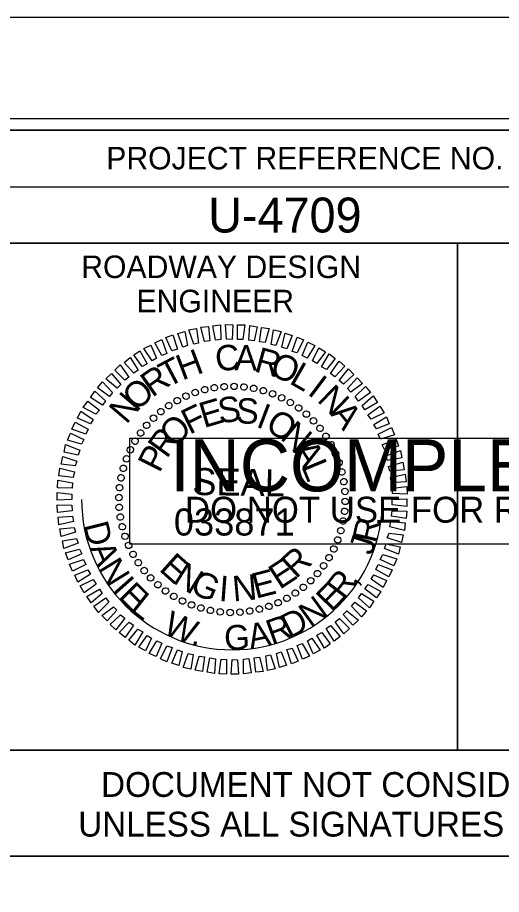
# Model space of a CAD drawing. Extents: x 1779926 to 1781626, y 618464 to 619564.
# Drawn here: x 1781395.5 to 1781502.7, y 619369.7 to 619564.2 of the extents above; entities that cross this region are included whole.
import ezdxf

# ---------------------------------------------------------------- set-up
doc = ezdxf.new("R2010")
doc.units = 0
for name, color, linetype in [('Old_Level_58', 7, 'Continuous'), ('Scratch_Level_0', 7, 'Continuous'), ('Sheet Data Field CELL', 7, 'Continuous'), ('Sheet Plot Border Inside CELL', 7, 'Continuous'), ('Sheet Plot Border Outside CELL', 7, 'Continuous'), ('Sheet Professional Seal CELL', 7, 'Continuous'), ('Sheet Profile CELL', 7, 'Continuous'), ('Sheet Profile Grid Major CELL', 7, 'Continuous'), ('Sheet Profile Grid Minor CELL', 7, 'Continuous'), ('Sheet Sticker Exception Certification CELL', 7, 'Continuous'), ('Sheet Sticker Incomplete CELL', 7, 'Continuous')]:
    doc.layers.add(name, color=color, linetype=linetype)

msp = doc.modelspace()

# ---------------------------------------------------------------- linework, layer by layer
at = {"layer": 'Old_Level_58'}
msp.add_lwpolyline([(1781392.9, 619378.14), (1781592.95, 619378.14), (1781592.95, 619314.19), (1781392.9, 619314.19)], close=True, dxfattribs=at)
at = {"layer": 'Scratch_Level_0'}
msp.add_arc((1781443.01, 619457.29), 33.36, 180, 360, dxfattribs=at)
at = {"layer": 'Sheet Plot Border Inside CELL'}
msp.add_lwpolyline([(1779938.96, 618486.64), (1781605.46, 618486.64), (1781605.46, 619541.74), (1779938.96, 619541.74)], close=True, dxfattribs=at)
at = {"layer": 'Sheet Plot Border Outside CELL'}
msp.add_lwpolyline([(1779925.96, 618464.19), (1781625.96, 618464.19), (1781625.96, 619564.19), (1779925.96, 619564.19)], close=True, dxfattribs=at)
at = {"layer": 'Sheet Professional Seal CELL'}
for p, q in [((1781434.81, 619481.04), (1781434.81, 619481.04)), ((1781436.91, 619481.64), (1781436.91, 619481.64)), ((1781439.11, 619482.04), (1781439.11, 619482.04)), ((1781441.26, 619482.34), (1781441.26, 619482.34)), ((1781443.46, 619482.39), (1781443.46, 619482.39)), ((1781445.66, 619482.24), (1781445.66, 619482.24)), ((1781447.81, 619481.89), (1781447.81, 619481.89)), ((1781449.91, 619481.44), (1781449.91, 619481.44)), ((1781430.86, 619479.24), (1781430.86, 619479.24)), ((1781432.81, 619480.24), (1781432.81, 619480.24)), ((1781452.01, 619480.74), (1781452.01, 619480.74)), ((1781454.01, 619479.84), (1781454.01, 619479.84)), ((1781428.96, 619478.09), (1781428.96, 619478.09)), ((1781455.96, 619478.84), (1781455.96, 619478.84)), ((1781457.76, 619477.59), (1781457.76, 619477.59)), ((1781425.56, 619475.34), (1781425.56, 619475.34)), ((1781427.21, 619476.84), (1781427.21, 619476.84)), ((1781459.51, 619476.24), (1781459.51, 619476.24)), ((1781424.06, 619473.79), (1781424.06, 619473.79)), ((1781461.06, 619474.74), (1781461.06, 619474.74)), ((1781422.71, 619472.04), (1781422.71, 619472.04)), ((1781462.56, 619473.09), (1781462.56, 619473.09)), ((1781463.81, 619471.34), (1781463.81, 619471.34)), ((1781421.46, 619470.24), (1781421.46, 619470.24)), ((1781464.96, 619469.44), (1781464.96, 619469.44)), ((1781420.46, 619468.29), (1781420.46, 619468.29)), ((1781465.96, 619467.49), (1781465.96, 619467.49)), ((1781419.56, 619466.29), (1781419.56, 619466.29)), ((1781466.76, 619465.49), (1781466.76, 619465.49)), ((1781418.86, 619464.19), (1781418.86, 619464.19)), ((1781418.41, 619462.09), (1781418.41, 619462.09)), ((1781467.36, 619463.39), (1781467.36, 619463.39)), ((1781418.06, 619459.94), (1781418.06, 619459.94)), ((1781467.76, 619461.19), (1781467.76, 619461.19)), ((1781417.91, 619457.74), (1781417.91, 619457.74)), ((1781468.06, 619459.04), (1781468.06, 619459.04)), ((1781443.01, 619457.29), (1781443.01, 619457.29)), ((1781468.11, 619456.84), (1781468.11, 619456.84)), ((1781417.96, 619455.54), (1781417.96, 619455.54)), ((1781467.96, 619454.64), (1781467.96, 619454.64)), ((1781418.26, 619453.39), (1781418.26, 619453.39)), ((1781467.61, 619452.49), (1781467.61, 619452.49)), ((1781418.66, 619451.19), (1781418.66, 619451.19)), ((1781467.16, 619450.39), (1781467.16, 619450.39)), ((1781419.26, 619449.09), (1781419.26, 619449.09)), ((1781466.46, 619448.29), (1781466.46, 619448.29)), ((1781420.06, 619447.09), (1781420.06, 619447.09)), ((1781465.56, 619446.29), (1781465.56, 619446.29)), ((1781421.06, 619445.14), (1781421.06, 619445.14)), ((1781464.56, 619444.34), (1781464.56, 619444.34)), ((1781422.21, 619443.24), (1781422.21, 619443.24)), ((1781463.31, 619442.54), (1781463.31, 619442.54)), ((1781423.46, 619441.49), (1781423.46, 619441.49)), ((1781461.96, 619440.79), (1781461.96, 619440.79)), ((1781424.96, 619439.84), (1781424.96, 619439.84)), ((1781426.51, 619438.34), (1781426.51, 619438.34)), ((1781460.46, 619439.24), (1781460.46, 619439.24)), ((1781428.26, 619436.99), (1781428.26, 619436.99)), ((1781457.06, 619436.49), (1781457.06, 619436.49)), ((1781458.81, 619437.74), (1781458.81, 619437.74)), ((1781430.06, 619435.74), (1781430.06, 619435.74)), ((1781432.01, 619434.74), (1781432.01, 619434.74)), ((1781453.21, 619434.34), (1781453.21, 619434.34)), ((1781455.16, 619435.34), (1781455.16, 619435.34)), ((1781434.01, 619433.84), (1781434.01, 619433.84)), ((1781436.11, 619433.14), (1781436.11, 619433.14)), ((1781438.21, 619432.69), (1781438.21, 619432.69)), ((1781446.91, 619432.54), (1781446.91, 619432.54)), ((1781449.11, 619432.94), (1781449.11, 619432.94)), ((1781451.21, 619433.54), (1781451.21, 619433.54)), ((1781440.36, 619432.34), (1781440.36, 619432.34)), ((1781442.56, 619432.19), (1781442.56, 619432.19)), ((1781444.76, 619432.24), (1781444.76, 619432.24))]:
    msp.add_line(p, q, dxfattribs=at)
for points in [[(1781434.51, 619491.74), (1781433.46, 619494.89), (1781435.16, 619495.24), (1781435.56, 619491.99)], [(1781436.91, 619492.29), (1781436.11, 619495.49), (1781437.76, 619495.64), (1781438.11, 619492.44)], [(1781439.31, 619492.59), (1781438.76, 619495.79), (1781440.46, 619495.99), (1781440.51, 619492.74)], [(1781441.81, 619492.84), (1781441.56, 619496.09), (1781443.21, 619496.04), (1781443.01, 619492.79)], [(1781444.21, 619492.79), (1781444.21, 619496.04), (1781445.86, 619495.99), (1781445.41, 619492.74)], [(1781446.71, 619492.64), (1781446.91, 619495.89), (1781448.56, 619495.59), (1781447.91, 619492.44)], [(1781449.11, 619492.24), (1781449.56, 619495.44), (1781451.21, 619495.19), (1781450.31, 619492.09)], [(1781451.66, 619491.69), (1781452.16, 619494.94), (1781453.86, 619494.54), (1781452.71, 619491.44)], [(1781427.46, 619489.24), (1781425.86, 619492.04), (1781427.41, 619492.74), (1781428.56, 619489.69)], [(1781429.66, 619490.29), (1781428.36, 619493.19), (1781429.86, 619493.79), (1781430.91, 619490.59)], [(1781432.11, 619491.09), (1781430.96, 619494.09), (1781432.51, 619494.54), (1781433.16, 619491.44)], [(1781454.06, 619491.04), (1781454.81, 619494.14), (1781456.36, 619493.64), (1781455.11, 619490.69)], [(1781456.31, 619490.14), (1781457.46, 619493.29), (1781458.86, 619492.69), (1781457.46, 619489.79)], [(1781425.31, 619488.04), (1781423.46, 619490.74), (1781425.01, 619491.54), (1781426.26, 619488.64)], [(1781458.56, 619489.19), (1781459.81, 619492.14), (1781461.36, 619491.44), (1781459.66, 619488.64)], [(1781460.86, 619488.04), (1781462.21, 619490.89), (1781463.71, 619490.04), (1781461.81, 619487.44)], [(1781423.11, 619486.79), (1781421.26, 619489.34), (1781422.56, 619490.29), (1781424.21, 619487.39)], [(1781462.81, 619486.69), (1781464.56, 619489.59), (1781465.86, 619488.54), (1781463.91, 619486.09)], [(1781419.21, 619483.74), (1781417.01, 619485.94), (1781418.21, 619487.14), (1781420.16, 619484.44)], [(1781421.21, 619485.29), (1781419.06, 619487.69), (1781420.41, 619488.74), (1781422.16, 619485.94)], [(1781464.86, 619485.19), (1781466.71, 619487.94), (1781468.01, 619486.84), (1781465.81, 619484.49)], [(1781417.56, 619481.99), (1781415.01, 619484.04), (1781416.26, 619485.19), (1781418.36, 619482.79)], [(1781466.76, 619483.64), (1781468.81, 619486.24), (1781470.01, 619485.04), (1781467.71, 619482.89)], [(1781415.81, 619480.09), (1781413.21, 619482.04), (1781414.31, 619483.34), (1781416.51, 619480.99)], [(1781468.56, 619481.89), (1781470.71, 619484.24), (1781471.91, 619483.04), (1781469.31, 619481.09)], [(1781414.31, 619478.19), (1781411.61, 619479.89), (1781412.56, 619481.34), (1781414.96, 619479.14)], [(1781470.31, 619480.09), (1781472.61, 619482.34), (1781473.66, 619480.99), (1781471.01, 619479.09)], [(1781412.81, 619476.19), (1781410.01, 619477.69), (1781411.01, 619479.09), (1781413.61, 619477.09)], [(1781471.81, 619478.14), (1781474.26, 619480.24), (1781475.21, 619478.79), (1781472.41, 619477.19)], [(1781473.11, 619476.09), (1781475.76, 619477.99), (1781476.71, 619476.49), (1781473.81, 619475.09)], [(1781411.61, 619474.04), (1781408.76, 619475.29), (1781409.51, 619476.84), (1781412.21, 619474.99)], [(1781474.41, 619473.89), (1781477.21, 619475.64), (1781477.86, 619474.09), (1781475.01, 619472.94)], [(1781410.61, 619471.74), (1781407.51, 619472.89), (1781408.26, 619474.44), (1781411.11, 619472.84)], [(1781475.41, 619471.74), (1781478.36, 619473.24), (1781479.01, 619471.64), (1781475.91, 619470.64)], [(1781409.61, 619469.54), (1781406.51, 619470.44), (1781407.16, 619471.99), (1781410.16, 619470.59)], [(1781408.86, 619467.14), (1781405.76, 619467.79), (1781406.11, 619469.44), (1781409.26, 619468.19)], [(1781476.31, 619469.39), (1781479.36, 619470.69), (1781479.91, 619469.14), (1781476.81, 619468.34)], [(1781477.11, 619466.99), (1781480.31, 619468.14), (1781480.61, 619466.49), (1781477.46, 619465.94)], [(1781408.21, 619464.74), (1781405.11, 619465.14), (1781405.46, 619466.84), (1781408.61, 619465.79)], [(1781477.71, 619464.59), (1781480.86, 619465.54), (1781481.16, 619463.84), (1781478.01, 619463.54)], [(1781407.81, 619462.19), (1781404.61, 619462.49), (1781404.81, 619464.19), (1781408.06, 619463.39)], [(1781478.16, 619462.19), (1781481.41, 619462.89), (1781481.56, 619461.19), (1781478.36, 619460.99)], [(1781407.56, 619459.79), (1781404.31, 619459.89), (1781404.41, 619461.54), (1781407.66, 619460.99)], [(1781478.46, 619459.79), (1781481.71, 619460.19), (1781481.81, 619458.49), (1781478.56, 619458.59)], [(1781407.51, 619457.29), (1781404.26, 619457.14), (1781404.26, 619458.84), (1781407.51, 619458.49)], [(1781407.56, 619454.79), (1781404.31, 619454.39), (1781404.21, 619456.09), (1781407.46, 619455.99)], [(1781478.51, 619457.29), (1781481.76, 619457.44), (1781481.76, 619455.74), (1781478.51, 619456.09)], [(1781478.46, 619454.79), (1781481.71, 619454.69), (1781481.61, 619453.04), (1781478.36, 619453.59)], [(1781407.86, 619452.39), (1781404.61, 619451.69), (1781404.46, 619453.39), (1781407.66, 619453.59)], [(1781478.21, 619452.39), (1781481.41, 619452.09), (1781481.21, 619450.39), (1781477.96, 619451.19)], [(1781408.31, 619449.99), (1781405.16, 619449.04), (1781404.86, 619450.74), (1781408.01, 619451.04)], [(1781408.91, 619447.59), (1781405.71, 619446.44), (1781405.41, 619448.09), (1781408.56, 619448.64)], [(1781477.81, 619449.84), (1781480.91, 619449.44), (1781480.56, 619447.74), (1781477.41, 619448.79)], [(1781409.71, 619445.19), (1781406.66, 619443.89), (1781406.11, 619445.44), (1781409.21, 619446.24)], [(1781477.16, 619447.44), (1781480.26, 619446.79), (1781479.91, 619445.14), (1781476.76, 619446.39)], [(1781476.41, 619445.04), (1781479.51, 619444.14), (1781478.86, 619442.59), (1781475.86, 619443.99)], [(1781410.61, 619442.84), (1781407.66, 619441.34), (1781407.01, 619442.94), (1781410.11, 619443.94)], [(1781475.41, 619442.84), (1781478.51, 619441.69), (1781477.76, 619440.14), (1781474.91, 619441.74)], [(1781411.61, 619440.69), (1781408.81, 619438.94), (1781408.16, 619440.49), (1781411.01, 619441.64)], [(1781474.41, 619440.54), (1781477.26, 619439.29), (1781476.51, 619437.74), (1781473.81, 619439.59)], [(1781412.91, 619438.49), (1781410.26, 619436.59), (1781409.31, 619438.09), (1781412.21, 619439.49)], [(1781473.21, 619438.39), (1781476.01, 619436.89), (1781475.01, 619435.49), (1781472.41, 619437.49)], [(1781414.21, 619436.44), (1781411.76, 619434.34), (1781410.81, 619435.79), (1781413.61, 619437.39)], [(1781471.71, 619436.39), (1781474.41, 619434.69), (1781473.46, 619433.24), (1781471.06, 619435.44)], [(1781415.71, 619434.49), (1781413.41, 619432.24), (1781412.36, 619433.59), (1781415.01, 619435.49)], [(1781470.21, 619434.49), (1781472.81, 619432.54), (1781471.71, 619431.24), (1781469.51, 619433.59)], [(1781417.46, 619432.69), (1781415.31, 619430.34), (1781414.11, 619431.54), (1781416.71, 619433.49)], [(1781468.46, 619432.59), (1781471.01, 619430.54), (1781469.76, 619429.39), (1781467.66, 619431.79)], [(1781419.26, 619430.94), (1781417.21, 619428.34), (1781416.01, 619429.54), (1781418.31, 619431.69)], [(1781466.81, 619430.84), (1781469.01, 619428.64), (1781467.81, 619427.44), (1781465.86, 619430.14)], [(1781421.16, 619429.39), (1781419.31, 619426.64), (1781418.01, 619427.74), (1781420.21, 619430.09)], [(1781423.21, 619427.89), (1781421.46, 619424.99), (1781420.16, 619426.04), (1781422.11, 619428.49)], [(1781464.81, 619429.29), (1781466.96, 619426.89), (1781465.61, 619425.84), (1781463.86, 619428.64)], [(1781425.16, 619426.54), (1781423.81, 619423.69), (1781422.31, 619424.54), (1781424.21, 619427.14)], [(1781462.91, 619427.79), (1781464.76, 619425.24), (1781463.46, 619424.29), (1781461.81, 619427.19)], [(1781427.46, 619425.39), (1781426.21, 619422.44), (1781424.66, 619423.14), (1781426.36, 619425.94)], [(1781429.71, 619424.44), (1781428.56, 619421.29), (1781427.16, 619421.89), (1781428.56, 619424.79)], [(1781458.56, 619425.34), (1781460.16, 619422.54), (1781458.61, 619421.84), (1781457.46, 619424.89)], [(1781460.71, 619426.54), (1781462.56, 619423.84), (1781461.01, 619423.04), (1781459.76, 619425.94)], [(1781431.96, 619423.54), (1781431.21, 619420.44), (1781429.66, 619420.94), (1781430.91, 619423.89)], [(1781434.36, 619422.89), (1781433.86, 619419.64), (1781432.16, 619420.04), (1781433.31, 619423.14)], [(1781451.51, 619422.84), (1781452.56, 619419.69), (1781450.86, 619419.34), (1781450.46, 619422.59)], [(1781453.91, 619423.49), (1781455.06, 619420.49), (1781453.51, 619420.04), (1781452.86, 619423.14)], [(1781456.36, 619424.29), (1781457.66, 619421.39), (1781456.16, 619420.79), (1781455.11, 619423.99)], [(1781436.91, 619422.34), (1781436.46, 619419.14), (1781434.81, 619419.39), (1781435.71, 619422.49)], [(1781439.31, 619421.94), (1781439.11, 619418.69), (1781437.46, 619418.99), (1781438.11, 619422.14)], [(1781441.81, 619421.79), (1781441.81, 619418.54), (1781440.16, 619418.59), (1781440.61, 619421.84)], [(1781444.21, 619421.74), (1781444.46, 619418.49), (1781442.81, 619418.54), (1781443.01, 619421.79)], [(1781446.71, 619421.99), (1781447.26, 619418.79), (1781445.56, 619418.59), (1781445.51, 619421.84)], [(1781449.11, 619422.29), (1781449.91, 619419.09), (1781448.26, 619418.94), (1781447.91, 619422.14)]]:
    msp.add_lwpolyline(points, close=True, dxfattribs=at)
for centre, major_axis in [((1781441.26, 619482.31), (-0.05, 0.718)), ((1781443.44, 619482.37), (0.013, 0.72)), ((1781445.63, 619482.23), (0.075, 0.716)), ((1781432.8, 619480.2), (-0.293, 0.658)), ((1781434.84, 619481), (-0.234, 0.681)), ((1781436.94, 619481.62), (-0.174, 0.699)), ((1781439.08, 619482.06), (-0.113, 0.711)), ((1781447.79, 619481.91), (0.137, 0.707)), ((1781449.92, 619481.4), (0.198, 0.692)), ((1781451.99, 619480.7), (0.258, 0.672)), ((1781430.85, 619479.22), (-0.349, 0.63)), ((1781454, 619479.83), (0.316, 0.647)), ((1781455.92, 619478.79), (0.371, 0.617)), ((1781427.22, 619476.78), (-0.453, 0.56)), ((1781428.98, 619478.08), (-0.403, 0.597)), ((1781457.75, 619477.58), (0.423, 0.582)), ((1781425.58, 619475.33), (-0.5, 0.518)), ((1781459.46, 619476.22), (0.472, 0.543)), ((1781461.05, 619474.71), (0.518, 0.5)), ((1781424.08, 619473.74), (-0.543, 0.472)), ((1781462.5, 619473.07), (0.56, 0.453)), ((1781422.72, 619472.03), (-0.582, 0.423)), ((1781463.8, 619471.31), (0.597, 0.403)), ((1781421.51, 619470.21), (-0.617, 0.371)), ((1781464.94, 619469.45), (0.63, 0.349)), ((1781420.46, 619468.28), (-0.647, 0.316)), ((1781465.92, 619467.49), (0.658, 0.293)), ((1781419.59, 619466.28), (-0.672, 0.258)), ((1781466.72, 619465.45), (0.681, 0.234)), ((1781418.9, 619464.2), (-0.692, 0.198)), ((1781467.34, 619463.36), (0.699, 0.174)), ((1781418.39, 619462.08), (-0.707, 0.137)), ((1781467.78, 619461.21), (0.711, 0.113)), ((1781418.06, 619459.91), (-0.716, 0.075)), ((1781468.02, 619459.04), (0.718, 0.05)), ((1781417.93, 619457.73), (-0.72, 0.013)), ((1781417.99, 619455.54), (-0.718, -0.05)), ((1781468.08, 619456.85), (0.72, -0.013)), ((1781418.23, 619453.37), (-0.711, -0.113)), ((1781467.95, 619454.67), (0.716, -0.075)), ((1781418.67, 619451.22), (-0.699, -0.174)), ((1781467.63, 619452.5), (0.707, -0.137)), ((1781419.29, 619449.12), (-0.681, -0.234)), ((1781467.11, 619450.38), (0.692, -0.198)), ((1781466.42, 619448.3), (0.672, -0.258)), ((1781420.09, 619447.09), (-0.658, -0.293)), ((1781465.55, 619446.3), (0.647, -0.316)), ((1781421.07, 619445.13), (-0.63, -0.349)), ((1781422.21, 619443.26), (-0.597, -0.403)), ((1781464.5, 619444.37), (0.617, -0.371)), ((1781423.52, 619441.51), (-0.56, -0.453)), ((1781463.3, 619442.55), (0.582, -0.423)), ((1781424.96, 619439.87), (-0.518, -0.5)), ((1781461.93, 619440.84), (0.543, -0.472)), ((1781426.55, 619438.36), (-0.472, -0.543)), ((1781458.79, 619437.8), (0.453, -0.56)), ((1781460.43, 619439.25), (0.5, -0.518)), ((1781428.26, 619437), (-0.423, -0.582)), ((1781430.09, 619435.79), (-0.371, -0.617)), ((1781457.03, 619436.5), (0.403, -0.597)), ((1781432.01, 619434.75), (-0.316, -0.647)), ((1781434.02, 619433.88), (-0.258, -0.672)), ((1781451.17, 619433.58), (0.234, -0.681)), ((1781453.21, 619434.38), (0.293, -0.658)), ((1781455.16, 619435.35), (0.349, -0.63)), ((1781436.09, 619433.18), (-0.198, -0.692)), ((1781438.22, 619432.67), (-0.137, -0.707)), ((1781440.38, 619432.35), (-0.075, -0.716)), ((1781442.57, 619432.21), (-0.013, -0.72)), ((1781444.76, 619432.27), (0.05, -0.718)), ((1781446.93, 619432.52), (0.113, -0.711)), ((1781449.07, 619432.95), (0.174, -0.699))]:
    msp.add_ellipse(centre, major_axis=major_axis, ratio=0.999708, dxfattribs=at)
at = {"layer": 'Sheet Profile CELL'}
for p, q in [((1781392.91, 619526.64), (1781592.96, 619526.64)), ((1781492.96, 619514.14), (1781492.96, 619401.69))]:
    msp.add_line(p, q, dxfattribs=at)
for points in [[(1781592.96, 619539.19), (1780092.96, 619539.19), (1780092.96, 618489.19), (1781592.96, 618489.19)], [(1781392.91, 619539.19), (1781592.96, 619539.19), (1781592.96, 619514.14), (1781392.91, 619514.14)], [(1781392.91, 619514.14), (1781492.96, 619514.14), (1781492.96, 619401.64), (1781392.91, 619401.64)], [(1781492.96, 619514.14), (1781592.96, 619514.14), (1781592.96, 619401.64), (1781492.96, 619401.64)]]:
    msp.add_lwpolyline(points, close=True, dxfattribs=at)
at = {"layer": 'Sheet Profile Grid Major CELL'}
msp.add_lwpolyline([(1780942.96, 619039.19), (1780992.96, 619039.19), (1780992.96, 619539.19), (1781042.96, 619539.19), (1781042.96, 619039.19), (1781092.96, 619039.19), (1781092.96, 619539.19), (1781142.96, 619539.19), (1781142.96, 619039.19), (1781192.96, 619039.19), (1781192.96, 619539.19), (1781242.96, 619539.19), (1781242.96, 619039.19), (1781292.96, 619039.19), (1781292.96, 619539.19), (1781342.96, 619539.19), (1781342.96, 619039.19), (1781392.96, 619039.19), (1781392.96, 619539.19), (1781419.26, 619539.19)], dxfattribs=at)
at = {"layer": 'Sheet Profile Grid Minor CELL'}
msp.add_lwpolyline([(1781387.96, 619539.19), (1781397.96, 619539.19)], dxfattribs=at)
at = {"layer": 'Sheet Sticker Exception Certification CELL'}
for p, q in [((1781392.91, 619401.64), (1781592.95, 619401.64)), ((1781392.91, 619401.64), (1781592.95, 619401.64)), ((1781592.95, 619378.14), (1781392.91, 619378.14)), ((1781592.95, 619378.14), (1781392.91, 619378.14))]:
    msp.add_line(p, q, dxfattribs=at)
at = {"layer": 'Sheet Sticker Incomplete CELL'}
msp.add_lwpolyline([(1781420.37, 619447.38), (1781420.37, 619470.88), (1781567.37, 619470.88), (1781567.37, 619447.38)], close=True, dxfattribs=at)

# ---------------------------------------------------------------- texts
at = {"layer": 'Sheet Data Field CELL'}
msp.add_text('U-4709', height=7.75, dxfattribs=at).set_placement((1781437.72, 619516.5))
at = {"layer": 'Sheet Professional Seal CELL'}
for s, height, rotation, p in [('C', 5.64, 6.2199, (1781439.56, 619485.64)), ('A', 5.64, 359.0203, (1781443.51, 619485.94)), ('R', 5.64, 344.6211, (1781447.71, 619485.74)), ('T', 5.64, 27.8198, (1781428.71, 619481.99)), ('H', 5.64, 20.6195, (1781431.96, 619483.64)), ('O', 5.64, 337.4212, (1781451.06, 619484.99)), ('L', 5.64, 330.2209, (1781455.46, 619483.14)), ('R', 5.64, 35.0205, (1781425.31, 619479.79)), ('O', 5.64, 42.2217, (1781421.86, 619476.69)), ('I', 5.64, 323.0201, (1781459.51, 619480.74)), ('N', 5.64, 49.4235, (1781419.56, 619473.79)), ('N', 5.64, 315.8189, (1781461.66, 619479.19)), ('E', 5.64, 16.6111, (1781436.76, 619473.09)), ('S', 5.64, 7.2556, (1781440.21, 619474.14)), ('S', 5.64, 357.9004, (1781443.81, 619474.19)), ('F', 5.64, 25.967, (1781433.56, 619471.59)), ('I', 5.64, 339.1896, (1781448.11, 619473.49)), ('A', 5.64, 308.6172, (1781464.61, 619476.24)), ('O', 5.64, 44.6812, (1781430.26, 619468.64)), ('O', 5.64, 329.8335, (1781450.11, 619472.79)), ('N', 5.64, 320.4766, (1781453.46, 619470.79)), ('R', 5.64, 54.0397, (1781428.51, 619466.19)), ('A', 5.64, 301.7603, (1781456.31, 619468.19)), ('P', 5.64, 63.3989, (1781426.91, 619462.99)), ('L', 5.64, 292.4008, (1781458.26, 619464.74)), ('SEAL', 5.998, 359, (1781434.16, 619458.29)), ('R', 5.64, 42.4814, (1781457.11, 619439.54)), ('E', 5.64, 318.2769, (1781426.61, 619441.64)), ('E', 5.64, 33.1241, (1781453.56, 619437.19)), ('N', 5.64, 327.634, (1781429.61, 619438.94)), ('G', 5.64, 336.9902, (1781433.41, 619436.69)), ('I', 5.64, 355.7012, (1781439.96, 619434.79)), ('N', 5.64, 5.0564, (1781443.31, 619434.64)), ('E', 5.64, 14.4118, (1781448.26, 619435.24))]:
    msp.add_text(s, height=height, rotation=rotation, dxfattribs=at).set_placement(p)
at = {"layer": 'Sheet Profile CELL'}
for s, height, p in [('PROJECT REFERENCE NO.', 5.0001, (1781415.12, 619530.5)), ('ROADWAY DESIGN', 5.0001, (1781409.57, 619506.4)), ('ENGINEER', 5, (1781421.82, 619498.8))]:
    msp.add_text(s, height=height, dxfattribs=at).set_placement(p)
at = {"layer": 'Sheet Profile Grid Minor CELL'}
msp.add_text('033871', height=5.998, dxfattribs=at).set_placement((1781430.11, 619449.28))
for s, rotation, p in [('D', 284.2682, (1781410.02, 619451.65)), ('R', 77.3541, (1781474.98, 619447.39)), ('.', 84.2805, (1781475.94, 619451.32)), ('J', 72.4855, (1781474.02, 619444.71)), ('A', 293.4128, (1781411.33, 619446.48)), ('N', 301.5986, (1781413.19, 619442.08)), ('I', 311.5304, (1781416.26, 619437.16)), ('R', 52.3788, (1781467.81, 619434.81)), ('E', 315.0508, (1781417.55, 619435.56)), ('E', 45.7958, (1781465.07, 619432.12)), (',', 59.3052, (1781470.34, 619437.97)), ('L', 321.6338, (1781420.21, 619432.78)), ('N', 35.8641, (1781460.39, 619428.69)), ('W', 336.8891, (1781427.46, 619427.65)), ('D', 26.7195, (1781455.63, 619426.29)), ('R', 19.793, (1781451.8, 619425)), ('G', 1.6755, (1781441.32, 619423.86)), ('A', 11.6072, (1781447.11, 619424.07)), ('.', 348.4952, (1781433.74, 619425.13))]:
    msp.add_text(s, height=5.5, rotation=rotation, dxfattribs=at).set_placement(p)
at = {"layer": 'Sheet Sticker Exception Certification CELL'}
for s, p in [('DOCUMENT NOT CONSIDERED FINAL', (1781413.98, 619391.3)), ('DOCUMENT NOT CONSIDERED FINAL', (1781413.98, 619391.3)), ('UNLESS ALL SIGNATURES COMPLETED', (1781408.91, 619382.5)), ('UNLESS ALL SIGNATURES COMPLETED', (1781408.91, 619382.5))]:
    msp.add_text(s, height=5.5, dxfattribs=at).set_placement(p)
at = {"layer": 'Sheet Sticker Incomplete CELL'}
for s, height, p in [('INCOMPLETE PLANS', 11.52, (1781429.32, 619459.08)), ('DO NOT USE FOR R/W ACQUISITION', 5.76, (1781432.57, 619452.13))]:
    msp.add_text(s, height=height, dxfattribs=at).set_placement(p)

doc.saveas('drawing.dxf')
